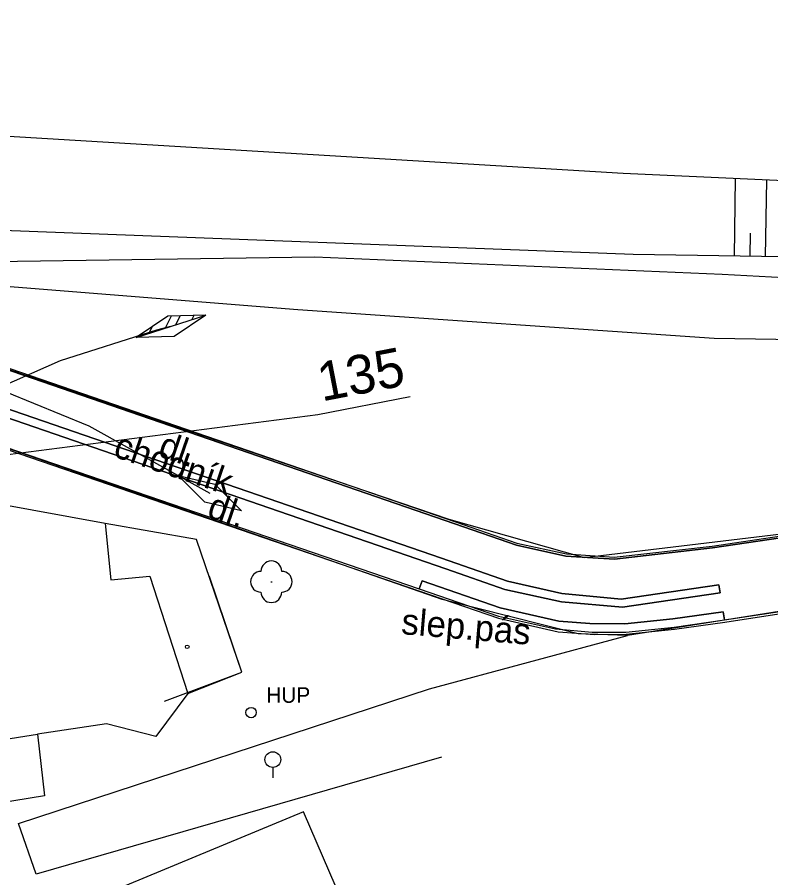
# Model space of a CAD drawing. Extents: x -545736 to -544888, y -1122892 to -1119128.
# Drawn here: x -545215.69 to -545179.41, y -1121503.39 to -1121461.96 of the extents above; entities that cross this region are included whole.
import ezdxf

# ---------------------------------------------------------------- set-up
doc = ezdxf.new("R2010")
doc.units = 0
for name, color, linetype in [('Implicitní', 7, 'Continuous'), ('Podbarveni_Komunikace', 7, 'Continuous'), ('so180602', 7, 'Continuous'), ('Vrstva 16_plochy', 7, 'Continuous'), ('Vrstva 23', 7, 'Continuous'), ('Vrstva 31', 7, 'Continuous'), ('Vrstva 36', 7, 'Continuous'), ('Vrstva 37', 7, 'Continuous'), ('Vrstva 48', 7, 'Continuous'), ('Vrstva 49', 7, 'Continuous'), ('Vrstva 50', 7, 'Continuous'), ('Vrstva 51', 7, 'Continuous'), ('Vrstva 59', 7, 'Continuous'), ('Vrstva 62', 7, 'Continuous'), ('Vrstva 63', 7, 'Continuous')]:
    doc.layers.add(name, color=color, linetype=linetype)

msp = doc.modelspace()

# ---------------------------------------------------------------- linework, layer by layer
at = {"layer": 'Implicitní'}
for p, q in [((-545221.081, -1121497.447), (-545214.715, -1121496.482)), ((-545214.715, -1121496.482), (-545214.376, -1121499.44)), ((-545214.376, -1121499.44), (-545220.499, -1121500.463))]:
    msp.add_line(p, q, dxfattribs=at)
at = {"layer": 'Podbarveni_Komunikace'}
for p, q in [((-545192.213, -1121489.507), (-545189.495, -1121490.1)), ((-545181.848, -1121489.675), (-545181.915, -1121489.285)), ((-545181.642, -1121490.979), (-545173.652, -1121489.763)), ((-545181.698, -1121490.583), (-545184.127, -1121490.917)), ((-545181.698, -1121490.583), (-545181.642, -1121490.979)), ((-545181.642, -1121490.979), (-545181.698, -1121490.583)), ((-545184.06, -1121491.324), (-545181.642, -1121490.979))]:
    msp.add_line(p, q, dxfattribs=at)
for points in [[(-545282.463, -1121464.291), (-545282.502, -1121466.155), (-545278.701, -1121466.513), (-545277.62, -1121466.604), (-545264.505, -1121467.876), (-545246.814, -1121469.541), (-545221.81, -1121478.869), (-545195.261, -1121488.008), (-545192.086, -1121489.117), (-545189.47, -1121489.707), (-545186.622, -1121489.972), (-545181.915, -1121489.285)], [(-545181.915, -1121489.285), (-545181.848, -1121489.675), (-545186.558, -1121490.367), (-545189.495, -1121490.1), (-545192.213, -1121489.507), (-545195.064, -1121488.511), (-545221.941, -1121479.258), (-545246.915, -1121469.939), (-545264.496, -1121468.276), (-545277.652, -1121467.005), (-545278.732, -1121466.919), (-545282.525, -1121466.557)], [(-545278.809, -1121468.208), (-545277.759, -1121468.263), (-545259.265, -1121469.989), (-545247.248, -1121471.157), (-545222.486, -1121480.519), (-545196.333, -1121489.476), (-545196.202, -1121489.093), (-545192.437, -1121490.398), (-545189.609, -1121491.03), (-545188.119, -1121491.155), (-545186.432, -1121491.166), (-545184.127, -1121490.917), (-545181.698, -1121490.583)], [(-545181.915, -1121489.285), (-545186.622, -1121489.972), (-545189.47, -1121489.707), (-545192.086, -1121489.117), (-545195.261, -1121488.008), (-545221.81, -1121478.869), (-545246.814, -1121469.541)], [(-545246.915, -1121469.939), (-545221.941, -1121479.258), (-545195.064, -1121488.511), (-545192.213, -1121489.507)], [(-545191.655, -1121487.377), (-545194.62, -1121486.345), (-545221.128, -1121477.216)], [(-545173.926, -1121486.28), (-545182.217, -1121487.506), (-545186.931, -1121488.047)], [(-545186.931, -1121488.047), (-545189.282, -1121487.905), (-545191.655, -1121487.377)], [(-545192.437, -1121490.398), (-545196.202, -1121489.093), (-545196.333, -1121489.476)], [(-545196.333, -1121489.476), (-545192.522, -1121490.794), (-545189.77, -1121491.401), (-545188.012, -1121491.57), (-545186.399, -1121491.562), (-545184.06, -1121491.324)], [(-545189.495, -1121490.1), (-545186.558, -1121490.367), (-545181.848, -1121489.675)], [(-545188.119, -1121491.155), (-545189.609, -1121491.03), (-545192.437, -1121490.398)], [(-545184.127, -1121490.917), (-545186.432, -1121491.166), (-545188.119, -1121491.155)]]:
    msp.add_lwpolyline(points, dxfattribs=at)
at = {"layer": 'Vrstva 16_plochy'}
for points in [[(-545282.463, -1121464.291), (-545282.502, -1121466.155), (-545278.701, -1121466.513), (-545277.62, -1121466.604), (-545264.505, -1121467.876), (-545246.814, -1121469.541), (-545221.81, -1121478.869), (-545195.261, -1121488.008), (-545192.086, -1121489.117), (-545189.47, -1121489.707), (-545186.622, -1121489.972), (-545181.915, -1121489.285)], [(-545282.463, -1121464.291), (-545278.525, -1121464.709), (-545277.47, -1121464.826), (-545264.343, -1121466.071), (-545246.296, -1121467.778), (-545221.128, -1121477.216), (-545194.62, -1121486.345), (-545191.655, -1121487.377), (-545189.282, -1121487.905), (-545186.931, -1121488.047), (-545182.217, -1121487.506), (-545173.926, -1121486.28), (-545169.693, -1121489.016)], [(-545282.502, -1121466.155), (-545282.525, -1121466.557), (-545278.732, -1121466.919), (-545277.652, -1121467.005), (-545264.496, -1121468.276), (-545246.915, -1121469.939), (-545221.941, -1121479.258), (-545195.064, -1121488.511), (-545192.213, -1121489.507), (-545189.495, -1121490.1), (-545186.558, -1121490.367), (-545181.848, -1121489.675), (-545181.915, -1121489.285)], [(-545282.525, -1121466.557), (-545282.646, -1121467.952), (-545278.809, -1121468.208), (-545277.759, -1121468.263), (-545259.265, -1121469.989), (-545247.248, -1121471.157), (-545222.486, -1121480.519), (-545196.333, -1121489.476), (-545196.202, -1121489.093), (-545192.437, -1121490.398), (-545189.609, -1121491.03), (-545188.119, -1121491.155), (-545186.432, -1121491.166), (-545184.127, -1121490.917), (-545181.698, -1121490.583)], [(-545247.248, -1121471.157), (-545247.227, -1121471.259), (-545222.54, -1121480.594), (-545196.361, -1121489.584), (-545192.528, -1121490.896), (-545189.644, -1121491.546), (-545187.881, -1121491.684), (-545186.379, -1121491.659), (-545184.053, -1121491.428), (-545181.624, -1121491.08), (-545173.616, -1121489.852)], [(-545247.248, -1121471.157), (-545222.486, -1121480.519), (-545196.333, -1121489.476), (-545192.522, -1121490.794), (-545189.77, -1121491.401), (-545188.012, -1121491.57), (-545186.399, -1121491.562), (-545184.06, -1121491.324), (-545181.642, -1121490.979), (-545173.652, -1121489.763)], [(-545173.926, -1121486.28), (-545182.217, -1121487.506), (-545186.931, -1121488.047), (-545189.282, -1121487.905), (-545191.655, -1121487.377), (-545194.62, -1121486.345), (-545221.128, -1121477.216)], [(-545221.048, -1121477.16), (-545194.597, -1121486.247), (-545191.632, -1121487.28), (-545189.246, -1121487.797), (-545186.951, -1121487.962), (-545182.238, -1121487.421), (-545173.952, -1121486.182)], [(-545196.333, -1121489.476), (-545192.522, -1121490.794), (-545189.77, -1121491.401), (-545188.012, -1121491.57), (-545186.399, -1121491.562), (-545184.06, -1121491.324), (-545181.642, -1121490.979), (-545181.698, -1121490.583)], [(-545181.642, -1121490.979), (-545173.652, -1121489.763)]]:
    msp.add_lwpolyline(points, dxfattribs=at)
at = {"layer": 'Vrstva 23'}
msp.add_lwpolyline([(-545163.43, -1121599.323), (-545162.461, -1121598.907), (-545168.549, -1121583.825), (-545167.585, -1121583.378), (-545173.378, -1121570.042), (-545193.53, -1121520.81), (-545196.125, -1121513.956), (-545200.025, -1121504.563), (-545201.914, -1121500.208), (-545214.824, -1121505.578), (-545215.505, -1121504.469), (-545216.906, -1121505.087), (-545216.548, -1121506.16), (-545216.91, -1121506.413), (-545199.14, -1121549.483)], dxfattribs=at)
at = {"layer": 'Vrstva 31'}
for p, q in [((-545208.273, -1121476.358), (-545208.568, -1121476.929)), ((-545207.842, -1121476.334), (-545208.065, -1121476.768)), ((-545207.18, -1121476.314), (-545207.286, -1121476.519)), ((-545206.761, -1121476.313), (-545206.801, -1121476.364)), ((-545209.17, -1121476.835), (-545209.346, -1121477.178)), ((-545209.796, -1121477.264), (-545209.83, -1121477.332))]:
    msp.add_line(p, q, dxfattribs=at)
for points in [[(-545315.04, -1121463.02), (-545312.99, -1121462.45), (-545309.58, -1121461.96), (-545306.62, -1121462.09), (-545303.24, -1121463.82), (-545301.83, -1121464.25), (-545296.58, -1121464.73), (-545284.1, -1121465.64), (-545253.45, -1121468.37), (-545250.1, -1121468.83), (-545240.51, -1121471.66), (-545238.66, -1121472.31), (-545229.84, -1121475.26), (-545219.58, -1121478.88), (-545216.53, -1121479.77), (-545213.6, -1121478.49), (-545208.97, -1121477.01), (-545208.29, -1121476.84)], [(-545303.3, -1121464.13), (-545301.83, -1121464.25), (-545296.58, -1121464.73), (-545284.1, -1121465.64), (-545253.45, -1121468.37), (-545250.1, -1121468.83), (-545240.51, -1121471.66), (-545238.66, -1121472.31), (-545229.84, -1121475.26), (-545219.58, -1121478.88), (-545216.53, -1121479.77), (-545216.24, -1121480), (-545212.24, -1121481.63), (-545206.42, -1121484.87)], [(-545206.612, -1121476.304), (-545208.135, -1121477.325), (-545209.968, -1121477.376)], [(-545207.949, -1121484.019), (-545206.177, -1121484.433), (-545204.891, -1121485.721), (-545206.663, -1121485.307), (-545207.949, -1121484.019)]]:
    msp.add_lwpolyline(points, dxfattribs=at)
msp.add_lwpolyline([(-545206.612, -1121476.304), (-545208.445, -1121476.355), (-545209.968, -1121477.376)], close=True, dxfattribs=at)
at = {"layer": 'Vrstva 36'}
msp.add_line((-545203.385, -1121498.079), (-545203.384, -1121498.579), dxfattribs=at)
msp.add_circle((-545203.385, -1121497.701), 0.378, dxfattribs=at)
at = {"layer": 'Vrstva 37'}
msp.add_circle((-545204.43, -1121495.437), 0.25, dxfattribs=at)
at = {"layer": 'Vrstva 48'}
for p, q in [((-545181.164, -1121473.457), (-545181.109, -1121469.732)), ((-545179.664, -1121473.479), (-545179.609, -1121469.8)), ((-545180.414, -1121473.468), (-545180.398, -1121472.358))]:
    msp.add_line(p, q, dxfattribs=at)
at = {"layer": 'Vrstva 49'}
for points in [[(-545154.71, -1121470.935), (-545175.596, -1121469.983), (-545186.518, -1121469.486), (-545233.164, -1121466.668)], [(-545155.917, -1121474.08), (-545174.708, -1121473.553), (-545186.032, -1121473.385), (-545216.388, -1121472.226), (-545230.339, -1121471.574)]]:
    msp.add_lwpolyline(points, dxfattribs=at)
at = {"layer": 'Vrstva 50'}
msp.add_line((-545203.486, -1121489.139), (-545203.416, -1121489.139), dxfattribs=at)
for centre, start, end in [((-545203.456, -1121488.638), 0, 180), ((-545203.956, -1121489.138), 90, 270), ((-545202.956, -1121489.138), 270, 90), ((-545203.456, -1121489.638), 180, 0)]:
    msp.add_arc(centre, 0.5, start, end, dxfattribs=at)
at = {"layer": 'Vrstva 51'}
for p, q in [((-545211.449, -1121486.334), (-545241.836, -1121480.794)), ((-545207.06, -1121487.098), (-545211.449, -1121486.334)), ((-545211.449, -1121486.334), (-545211.177, -1121489.053)), ((-545204.879, -1121493.485), (-545207.06, -1121487.098)), ((-545211.177, -1121489.053), (-545209.301, -1121488.866)), ((-545209.301, -1121488.866), (-545207.469, -1121494.519)), ((-545207.469, -1121494.519), (-545204.879, -1121493.485)), ((-545207.469, -1121494.519), (-545209.024, -1121496.586)), ((-545211.389, -1121495.977), (-545214.715, -1121496.482)), ((-545209.024, -1121496.586), (-545211.389, -1121495.977)), ((-545195.258, -1121497.587), (-545214.773, -1121503.224))]:
    msp.add_line(p, q, dxfattribs=at)
for points in [[(-545226.678, -1121475.26), (-545216.81, -1121478.673), (-545194.915, -1121486.132), (-545188.396, -1121487.965), (-545173.81, -1121486.225), (-545169.577, -1121489.085)], [(-545169.577, -1121489.085), (-545186.315, -1121491.728), (-545188.683, -1121491.647), (-545195.23, -1121489.987), (-545217.66, -1121482.195), (-545227.595, -1121478.758)], [(-545208.592, -1121494.887), (-545204.879, -1121493.485), (-545206.437, -1121488.883)], [(-545195.849, -1121494.294), (-545186.315, -1121491.728)], [(-545214.773, -1121503.224), (-545215.628, -1121500.771), (-545195.849, -1121494.294)]]:
    msp.add_lwpolyline(points, dxfattribs=at)
at = {"layer": 'Vrstva 59'}
msp.add_circle((-545207.505, -1121492.273), 0.0873, dxfattribs=at)
at = {"layer": 'Vrstva 62'}
for points in [[(-545228.904, -1121473.893), (-545201.369, -1121473.494), (-545181.759, -1121474.323), (-545159.193, -1121475.553), (-545153.759, -1121475.212)], [(-545228.904, -1121473.893), (-545202.182, -1121476.033), (-545182.141, -1121477.405), (-545159.327, -1121477.78), (-545153.299, -1121477.563)]]:
    msp.add_lwpolyline(points, dxfattribs=at)
at = {"layer": 'Vrstva 63'}
for p, q in [((-545196.774, -1121480.237), (-545201.218, -1121481.101)), ((-545201.218, -1121481.101), (-545240.141, -1121486.132))]:
    msp.add_line(p, q, dxfattribs=at)

# ---------------------------------------------------------------- texts
at = {"layer": 'so180602'}
msp.add_text('135', height=1.875, rotation=10.9955, dxfattribs=at).set_placement((-545201.029, -1121480.465))
at = {"layer": 'Vrstva 16_plochy'}
for s, rotation, p in [('dl.', 341.0049, (-545208.969, -1121483.072)), ('dl.', 341.0945, (-545206.611, -1121486.004)), ('slep.pás', 355.2045, (-545197.228, -1121491.655))]:
    msp.add_text(s, height=1.25, rotation=rotation, dxfattribs=at).set_placement(p)
at = {"layer": 'Vrstva 36'}
msp.add_text('HUP', height=0.75, rotation=360, dxfattribs=at).set_placement((-545203.701, -1121494.967))
at = {"layer": 'Vrstva 51'}
msp.add_text('chodník', height=1.25, rotation=341.1875, dxfattribs=at).set_placement((-545211.123, -1121483.094))

doc.saveas('drawing.dxf')
